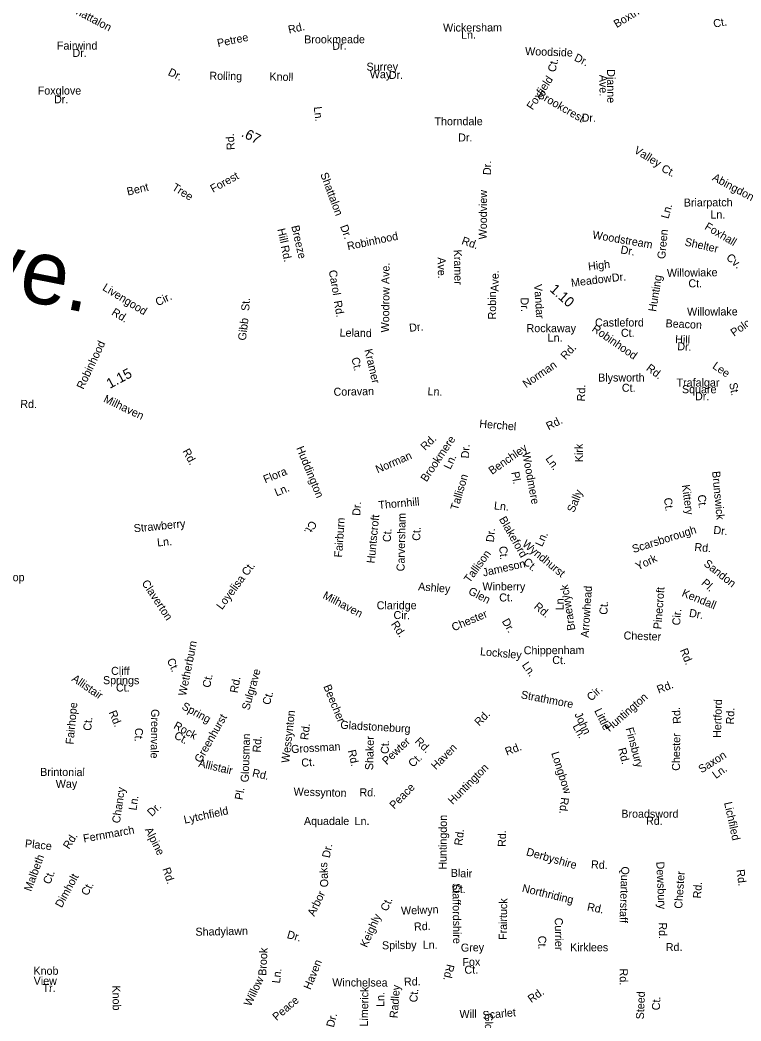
# Model space of a CAD drawing. Extents: x 1553981 to 1780076, y 812965 to 996873.
# Drawn here: x 1629823 to 1630892, y 848292 to 849777 of the extents above; entities that cross this region are included whole.
import ezdxf

# ---------------------------------------------------------------- set-up
doc = ezdxf.new("R2010")
doc.units = 0
for name, color, linetype in [('Exist Road Non-System Type 51 Label', 7, 'Continuous'), ('Exist Road Secondary Mileage Hundredths English Label', 7, 'Continuous'), ('Map Preparation Border Antique Large Shape', 7, 'Continuous')]:
    doc.layers.add(name, color=color, linetype=linetype)

msp = doc.modelspace()

# ---------------------------------------------------------------- texts
at = {"layer": 'Exist Road Non-System Type 51 Label'}
for s, height, rotation, p in [('Boxthorne', 11.87, 31.3922, (1630707.9, 849765)), ('Ct.', 11.88, 9.8757, (1630852.1, 849765.7)), ('Rd.', 11.88, 12.9036, (1630222.1, 849756.8)), ('Wickersham', 11.87, 0.1781, (1630450.4, 849759.9)), ('Ln.', 11.87, 0.1781, (1630477.2, 849749.3)), ('Petree', 11.88, 11.789, (1630116.7, 849736.8)), ('Brookmeade', 11.87, 0.1781, (1630244.5, 849742.4)), ('Dr.', 11.87, 0.8146, (1630286.2, 849732.8)), ('Woodside', 11.88, 358.1543, (1630571.9, 849725.1)), ('Ct.', 11.88, 77.4738, (1630616.9, 849699.1)), ('Dr.', 11.88, 333.7586, (1630643.8, 849717.4)), ('Surrey', 11.87, 0.1781, (1630336.9, 849701.9)), ('Way', 11.87, 0.1781, (1630341.8, 849690.7)), ('Dr.', 11.87, 0.1781, (1630370, 849689.7)), ('Dianne', 11.88, 270.4158, (1630693.5, 849704.1)), ('Rolling', 11.88, 359.1634, (1630103.8, 849688.6)), ('Knoll', 11.88, 358.1445, (1630192.8, 849687.6)), ('Foxfield', 11.88, 56.2308, (1630583.2, 849642.8)), ('Ave.', 11.88, 270.4158, (1630682.2, 849695.8)), ('Brookcrest', 11.88, 329.8936, (1630589.7, 849662.9)), ('Ln.', 11.87, 276.4955, (1630258.6, 849648.1)), ('Thorndale', 11.87, 0.1781, (1630437.7, 849620.9)), ('Dr.', 11.88, 359.1895, (1630655.8, 849626.4)), ('Rd.', 11.87, 93.6142, (1630141.6, 849584.6)), ('Dr.', 11.87, 0.1781, (1630472.8, 849596.9)), ('Valley', 11.88, 328.4345, (1630732.5, 849580.8)), ('Dr.', 11.88, 89.5136, (1630521.5, 849547.1)), ('Ct.', 11.88, 332.383, (1630773, 849553.2)), ('Forest', 11.88, 28.6979, (1630109.2, 849520.7)), ('Abingdon', 11.88, 331.74, (1630848.4, 849540)), ('Bent', 11.87, 13.7592, (1629983, 849516.6)), ('Tree', 11.88, 327.9451, (1630047.4, 849525.9)), ('Woodview', 11.88, 89.5136, (1630515.1, 849451.7)), ('Briarpatch', 11.88, 0.3783, (1630807.3, 849500.4)), ('Ln.', 11.88, 74.3344, (1630784.5, 849481.5)), ('Ln.', 11.88, 359.7932, (1630846.7, 849482.7)), ('Ave.', 95, 348.7973, (1629672.5, 849392)), ('Hill', 11.88, 282.9666, (1630204.5, 849466.7)), ('Breeze', 11.88, 282.763, (1630225.3, 849471.2)), ('Woodstream', 11.88, 350.2503, (1630671.2, 849453.2)), ('Green', 11.87, 84.6282, (1630779.7, 849422.2)), ('Foxhall', 11.88, 329.1319, (1630837.2, 849467.6)), ('Shelter', 11.88, 347.4622, (1630807.9, 849442.8)), ('Rd.', 11.88, 282.763, (1630209.6, 849441.5)), ('Kramer', 11.88, 271.2351, (1630466.2, 849436.4)), ('Dr.', 11.88, 350.2503, (1630712.9, 849431.1)), ('Ave.', 11.88, 271.2351, (1630442.2, 849425.1)), ('High', 11.88, 6.532, (1630666.1, 849405.6)), ('Cv.', 11.88, 318.2183, (1630869.3, 849423.3)), ('Carol', 11.88, 279.8235, (1630280.8, 849405.3)), ('Ave.', 11.87, 89.4313, (1630370.8, 849385.4)), ('Ave.', 11.88, 89.7261, (1630532.8, 849374.2)), ('Willowlake', 11.87, 0.7725, (1630782.4, 849396.1)), ('Meadow', 11.88, 7.1572, (1630640.9, 849381.3)), ('Dr.', 11.88, 5.4656, (1630701.1, 849388.8)), ('Hunting', 11.88, 80.7597, (1630766.2, 849343.9)), ('Ct.', 11.88, 359.3352, (1630814.1, 849380.7)), ('Livengood', 11.88, 328.3716, (1629944.4, 849377.2)), ('Woodrow', 11.88, 89.3796, (1630370.3, 849313.7)), ('Vandar', 11.88, 273.7771, (1630585.3, 849385)), ('Cir.', 11.88, 25.9069, (1630027.3, 849352.4)), ('St.', 11.88, 86.7419, (1630162.9, 849345.3)), ('Rd.', 11.88, 280.0506, (1630288.2, 849360)), ('Robin', 11.88, 89.7261, (1630528.9, 849333)), ('Dr.', 11.88, 272.5837, (1630565.2, 849365.3)), ('Rd.', 11.88, 328.3716, (1629957.8, 849340.6)), ('Willowlake', 11.88, 0.1325, (1630812.2, 849338.7)), ('Gibb', 11.87, 83.178, (1630157.9, 849301.2)), ('Beacon', 11.88, 357.401, (1630780.1, 849321.4)), ('Polo', 11.88, 34.8956, (1630881.8, 849307.1)), ('Leland', 11.88, 358.9235, (1630296.9, 849307.6)), ('Dr.', 11.88, 5.8843, (1630400.7, 849314.6)), ('Robinhood', 11.88, 64.5853, (1629917, 849228.4)), ('Hill', 11.88, 357.401, (1630794.3, 849297.9)), ('Kramer', 11.88, 283.2996, (1630333.6, 849287.8)), ('Rd.', 11.88, 47.0314, (1630632, 849272.4)), ('Dr.', 11.88, 357.401, (1630797.5, 849287.4)), ('Ct.', 11.88, 283.2996, (1630314.4, 849275.4)), ('Norman', 11.88, 34.4484, (1630573.5, 849230.9)), ('Lee', 11.88, 325.4495, (1630848.8, 849261.4)), ('Coravan', 11.88, 1.0678, (1630288.1, 849219.7)), ('Ln.', 11.88, 357.6763, (1630427.2, 849220.6)), ('Rd.', 11.88, 88.3833, (1630660.7, 849211.3)), ('St.', 11.87, 280.2859, (1630874.6, 849238.2)), ('Milhaven', 11.88, 334.6088, (1629945.8, 849211.1)), ('Herchel', 11.88, 355.2938, (1630503.8, 849172.7)), ('Rd.', 11.88, 26.9901, (1630606.8, 849168.5)), ('Rd.', 11.88, 44.536, (1630424, 849137.8)), ('Brookmere', 11.88, 55.9005, (1630425.8, 849091.1)), ('Rd.', 11.88, 298.9483, (1630063.5, 849137.5)), ('Huddington', 11.88, 292.2552, (1630232.4, 849142.2)), ('Dr.', 11.87, 87.3262, (1630488.8, 849126.7)), ('Benchley', 11.88, 34.9339, (1630523, 849102.3)), ('Kirk', 11.88, 90.2038, (1630657.7, 849121.3)), ('Norman', 11.88, 23.3308, (1630353.4, 849104.5)), ('Ln.', 11.88, 64.866, (1630461.3, 849109.6)), ('Woodmere', 11.88, 280.5077, (1630567.7, 849134.5)), ('Ln.', 11.88, 305.3065, (1630601.7, 849126.4)), ('Flora', 11.88, 22.2579, (1630186.7, 849089.7)), ('Brunswick', 11.87, 275.2973, (1630849.3, 849107.5)), ('Tallison', 11.88, 73.7258, (1630472.3, 849049.1)), ('Pl.', 11.88, 280.5077, (1630551.4, 849106.2)), ('Ln.', 11.88, 22.2579, (1630203.4, 849070.4)), ('Sally', 11.88, 67.7028, (1630644.6, 849045.7)), ('Kittery', 11.87, 278.1226, (1630804.3, 849087.1)), ('Thornhill', 11.88, 5.141, (1630355.1, 849051.7)), ('Ln.', 11.88, 354.3443, (1630525.5, 849051.3)), ('Ct.', 11.87, 278.1226, (1630777.7, 849067.8)), ('Ct.', 11.87, 275.2973, (1630828, 849072.6)), ('Dr.', 11.88, 86.0384, (1630327.5, 849041.4)), ('Strawberry', 11.88, 5.5425, (1629992.3, 849017.2)), ('Ct.', 11.87, 238.3786, (1630254.2, 849035.7)), ('Fairburn', 11.88, 86.0384, (1630300.6, 848979.6)), ('Huntscroft', 11.88, 84.5316, (1630348.9, 848970.8)), ('Carversham', 11.87, 88.8435, (1630393.2, 848959.3)), ('Blakeford', 11.88, 299.7713, (1630532.9, 849036.7)), ('Ct.', 11.88, 85.7668, (1630372.6, 849002.4)), ('Ct.', 11.87, 88.8435, (1630416.6, 849004.6)), ('Dr.', 11.87, 84.5537, (1630525.7, 849002.1)), ('Scarsborough', 11.875, 17.6674, (1630732.8, 848986.4)), ('Dr.', 11.88, 354.0217, (1630850.8, 849015.1)), ('Ln.', 11.88, 5.5425, (1630026.9, 848996.2)), ('Wyndhurst', 11.87, 320.5199, (1630566.8, 848998.1)), ('Ln.', 11.88, 65.2837, (1630597.2, 848994.9)), ('Tallison', 11.87, 53.81, (1630489.8, 848941.4)), ('Ct.', 11.88, 274.5531, (1630533.6, 848996.4)), ('Rd.', 11.88, 355.0182, (1630822.7, 848989.8)), ('Jameson', 11.88, 12.6818, (1630510.4, 848951.6)), ('Ct.', 11.88, 319.4659, (1630568.3, 848971.6)), ('York', 11.87, 25.4492, (1630739.4, 848960.6)), ('Sandon', 11.87, 321.5815, (1630835.9, 848968.8)), ('Ct.', 11.88, 53.1509, (1630160.1, 848951.6)), ('Claverton', 11.88, 303.5466, (1630002.9, 848942)), ('Loyelisa', 11.88, 53.1509, (1630122.6, 848901.6)), ('Pl.', 11.88, 317.8889, (1630832.4, 848940.8)), ('Milhaven', 11.88, 332.1808, (1630271, 848920.1)), ('Ashley', 11.88, 355.4223, (1630413.1, 848931.3)), ('Glen', 11.88, 332.6487, (1630486.8, 848926.3)), ('Winberry', 11.88, 359.6465, (1630508.7, 848931.3)), ('Braewyck', 11.88, 99.1579, (1630646.6, 848872.5)), ('Arrowhead', 11.88, 86.2124, (1630666.2, 848860.8)), ('Pinecroft', 11.88, 85.573, (1630773.9, 848873.1)), ('Kendall', 11.88, 337.7257, (1630803.4, 848922.9)), ('Claridge', 11.88, 0.1546, (1630352, 848903)), ('Ct.', 11.88, 0.6409, (1630533.7, 848914.6)), ('Ln.', 11.87, 89.1116, (1630629, 848901.5)), ('Cir.', 11.87, 359.0093, (1630376.8, 848888.7)), ('Chester', 11.88, 22.9264, (1630466.1, 848870.3)), ('Rd.', 11.88, 319.6172, (1630584.2, 848905.6)), ('Ct.', 11.88, 86.6633, (1630693.9, 848894.7)), ('Cir.', 11.88, 85.573, (1630801.8, 848878.9)), ('Dr.', 11.88, 350.0994, (1630814.5, 848892.2)), ('Rd.', 11.88, 303.714, (1630372.6, 848880.9)), ('Dr.', 11.88, 300.0169, (1630537.1, 848885.3)), ('Chester', 11.88, 358.1574, (1630717.9, 848858.4)), ('Wetherburn', 11.87, 78.546, (1630069.1, 848773.8)), ('Locksley', 11.87, 354.8455, (1630504.9, 848834.9)), ('Chippenham', 11.87, 0.2773, (1630570, 848836.3)), ('Rd.', 11.88, 292.0781, (1630801.3, 848842.4)), ('Ct.', 11.88, 293.8206, (1630040.6, 848827.5)), ('Ln.', 11.88, 304.7468, (1630566.7, 848820.2)), ('Ct.', 11.88, 359.1026, (1630612.2, 848822)), ('Cliff', 11.88, 359.8562, (1629958.1, 848805.8)), ('Sulgrave', 11.87, 74.0866, (1630162.9, 848752.6)), ('Allistair', 11.88, 325.5681, (1629898.7, 848797.7)), ('Springs', 11.88, 359.8562, (1629946.1, 848792)), ('Ct.', 11.87, 78.546, (1630104.9, 848786.1)), ('Rd.', 11.88, 79.5319, (1630145.7, 848778.2)), ('Rd.', 11.88, 21.0866, (1630770.1, 848777.9)), ('Ct.', 11.88, 359.8562, (1629965.3, 848781.1)), ('Beecher', 11.88, 292.1736, (1630272.6, 848788.7)), ('Strathmore', 11.88, 349.0968, (1630565.1, 848771.2)), ('Cir.', 11.88, 43.0647, (1630670.1, 848766.1)), ('Ct.', 11.87, 74.0866, (1630193.3, 848760.3)), ('Huntington', 11.88, 41.1128, (1630697.1, 848720.7)), ('Hertford', 11.87, 88.3163, (1630862.4, 848712.2)), ('Fairhope', 11.88, 84.5862, (1629902.3, 848702.2)), ('Rd.', 11.88, 292.0362, (1629954.5, 848750.3)), ('Greenvale', 11.88, 269.2383, (1630017.7, 848755.1)), ('Spring', 11.88, 331.2436, (1630061.7, 848755.8)), ('Wessynton', 11.87, 83.5865, (1630222.2, 848674.7)), ('Rd.', 11.88, 45.3748, (1630503.9, 848729.1)), ('Little', 11.88, 296.0144, (1630674.3, 848752.7)), ('Rd.', 11.88, 93.9483, (1630803.3, 848733.6)), ('Rd.', 11.87, 88.3163, (1630881.7, 848732.2)), ('Ct.', 11.88, 84.5862, (1629928.5, 848722.5)), ('Rock', 11.88, 331.2436, (1630049.7, 848727.1)), ('Greenhurst', 11.88, 60.219, (1630091.1, 848674.4)), ('Gladstoneburg', 11.875, 356.6584, (1630297.8, 848726)), ('John', 11.87, 295.1386, (1630645, 848747.4)), ('Ct.', 11.88, 268.0574, (1629993.7, 848727.3)), ('Ct.', 11.88, 331.2436, (1630050.5, 848712.5)), ('Rd.', 11.88, 82.6225, (1630250.2, 848708.7)), ('Ln.', 11.87, 298.8229, (1630642, 848729.7)), ('Finsbury', 11.88, 285.002, (1630720.9, 848726.3)), ('Glousman', 11.88, 88.2265, (1630162.1, 848646.3)), ('Rd.', 11.87, 85.8126, (1630179.6, 848690.3)), ('Shaker', 11.87, 88.3598, (1630346.6, 848664.4)), ('Ct.', 11.87, 88.3598, (1630369.8, 848688.4)), ('Pewter', 11.87, 43.7199, (1630366.8, 848671.6)), ('Rd.', 11.88, 315.8376, (1630407.7, 848706.2)), ('Chester', 11.87, 89.5554, (1630801.6, 848663.5)), ('Grossman', 11.87, 3.2688, (1630225.4, 848689.7)), ('Rd.', 11.87, 282.7231, (1630309.1, 848693.4)), ('Haven', 11.88, 45.3355, (1630439.7, 848664.2)), ('Rd.', 11.88, 21.0866, (1630545, 848685.9)), ('Longbow', 11.88, 287.6747, (1630610.6, 848689.8)), ('Rd.', 11.88, 285.002, (1630709.7, 848696)), ('Allistair', 11.88, 346.62, (1630087, 848669.7)), ('Ct.', 11.87, 3.2688, (1630240.5, 848669.6)), ('Ct.', 11.87, 43.7199, (1630405.6, 848667.8)), ('Saxon', 11.88, 32.6164, (1630833.7, 848659.6)), ('Brintonial', 11.88, 359.7474, (1629853, 848655.9)), ('Rd.', 11.88, 347.1539, (1630166.6, 848655.3)), ('Huntington', 11.88, 45.0883, (1630464.6, 848612.7)), ('Ln.', 11.88, 35.7842, (1630854.9, 848651.1)), ('Way', 11.87, 0.9148, (1629876.2, 848638.1)), ('Chancy', 11.87, 81.5292, (1629971.1, 848585.1)), ('Pl.', 11.88, 80.3066, (1630153, 848619.6)), ('Wessynton', 11.87, 358.3826, (1630228.6, 848626.9)), ('Rd.', 11.88, 359.4157, (1630326.4, 848625.7)), ('Peace', 11.88, 45.5988, (1630378, 848605.9)), ('Ln.', 11.87, 81.5292, (1629995.7, 848604.2)), ('Rd.', 11.88, 263.7807, (1630625.3, 848624.6)), ('Lichfiled', 11.87, 282.4681, (1630867, 848616.1)), ('Dr.', 11.88, 43.9881, (1630018.5, 848594.9)), ('Lytchfield', 11.88, 12.2052, (1630067.3, 848585)), ('Broadsword', 11.88, 359.9777, (1630714.7, 848593.9)), ('Aquadale', 11.88, 0.0294, (1630244.1, 848583.1)), ('Ln.', 11.88, 0.1121, (1630319.2, 848583)), ('Huntingdon', 11.88, 89.4901, (1630455.5, 848516.9)), ('Rd.', 11.87, 359.3455, (1630751.3, 848583.6)), ('Fernmarch', 11.88, 10.041, (1629917.8, 848557.1)), ('Alpine', 11.88, 296.5578, (1630007.8, 848576.3)), ('Rd.', 11.88, 83.0363, (1630478.6, 848552.1)), ('Rd.', 11.88, 89.0225, (1630543.4, 848550.5)), ('Place', 11.88, 353.7723, (1629830, 848550.1)), ('Rd.', 11.88, 57.3198, (1629895.9, 848546.3)), ('Dr.', 11.87, 78.98, (1630282.3, 848533.6)), ('Derbyshire', 11.88, 344.2276, (1630572.8, 848538.4)), ('Malbeth', 11.88, 69.675, (1629839.6, 848483.7)), ('Rd.', 11.88, 356.6379, (1630669.5, 848519.1)), ('Rd.', 11.88, 287.7932, (1630034.2, 848518.1)), ('Oaks', 11.87, 92.8866, (1630280.3, 848491.1)), ('Blair', 11.88, 357.9344, (1630461.6, 848506.3)), ('Quarterstaff', 11.875, 268.1774, (1630714.7, 848521.8)), ('Dewsbury', 11.88, 272.4251, (1630766.6, 848528.6)), ('Chester', 11.88, 86.1187, (1630804.9, 848458.6)), ('Rd.', 11.87, 277.288, (1630885.5, 848516.6)), ('Ct.', 11.88, 69.675, (1629867.8, 848494.3)), ('Dimholt', 11.88, 61.6823, (1629884.9, 848459.5)), ('Ct.', 11.88, 61.6823, (1629923.2, 848477.2)), ('Arbor', 11.87, 64.3648, (1630259.3, 848446.8)), ('Staffordshire', 11.875, 270.7025, (1630464.3, 848496.8)), ('Ct.', 11.88, 357.9344, (1630463.6, 848482.8)), ('Northriding', 11.875, 346.5423, (1630566.7, 848484.2)), ('Rd.', 11.88, 86.1187, (1630832.8, 848473.9)), ('Ct.', 11.88, 66.3224, (1630367.7, 848454.2)), ('Frairtuck', 11.88, 89.3364, (1630544.8, 848412.5)), ('Welwyn', 11.88, 2.3445, (1630388.3, 848450)), ('Rd.', 11.88, 348.8335, (1630663.2, 848456.5)), ('Keighly', 11.88, 65.7994, (1630337.4, 848400.5)), ('Rd.', 11.88, 2.3445, (1630407.5, 848426.5)), ('Currier', 11.88, 270.745, (1630616, 848445.6)), ('Shadylawn', 11.88, 1.1111, (1630083.4, 848418.8)), ('Dr.', 11.87, 344.0247, (1630218, 848415.7)), ('Rd.', 11.88, 270.3602, (1630770.3, 848438.7)), ('Spilsby', 11.88, 0.7689, (1630359.9, 848398.7)), ('Ln.', 11.87, 0.2406, (1630420.3, 848399.5)), ('Ct.', 11.88, 270.745, (1630591.4, 848418.8)), ('Brook', 11.88, 87.0503, (1630188.1, 848359.3)), ('Grey', 11.88, 1.2316, (1630476.9, 848395.2)), ('Kirklees', 11.88, 359.9346, (1630638.7, 848395.9)), ('Rd.', 11.88, 0.8989, (1630780.7, 848396)), ('Haven', 11.88, 67.8211, (1630253.8, 848338)), ('Fox', 11.88, 1.2316, (1630479.2, 848373.9)), ('Knob', 11.87, 359.8902, (1629843, 848361)), ('Ln.', 11.88, 83.5454, (1630208.5, 848347.8)), ('Rd.', 11.88, 257.0197, (1630456, 848377.5)), ('Ct.', 11.88, 1.2316, (1630482.2, 848362.4)), ('Rd.', 11.88, 270.4232, (1630712.3, 848370.2)), ('View', 11.87, 359.8902, (1629843.3, 848346.1)), ('Willow', 11.88, 64.6564, (1630165.1, 848313.2)), ('Winchelsea', 11.87, 359.8387, (1630286.1, 848343.7)), ('Rd.', 11.88, 1.1199, (1630392.5, 848344.8)), ('Tr.', 11.87, 359.8902, (1629856.5, 848335.5)), ('Knob', 11.87, 271.116, (1629960, 848345)), ('Limerick', 11.88, 88.9833, (1630338.8, 848284.2)), ('Radley', 11.88, 85.2954, (1630382.7, 848296.2)), ('Ct.', 11.88, 85.2954, (1630412.1, 848319.7)), ('Rd.', 11.88, 35.1897, (1630581.2, 848318.8)), ('Steed', 11.87, 87.6897, (1630748.1, 848294.7)), ('Peace', 11.88, 40.8114, (1630203.6, 848292.1)), ('Ln.', 11.88, 88.9833, (1630363.1, 848313.2)), ('Ct.', 11.87, 87.6897, (1630771.8, 848308.1)), ('Will', 11.87, 0.5668, (1630474.8, 848296.9)), ('Scarlet', 11.87, 5.294, (1630509.5, 848295)), ('Dr.', 11.87, 76.2693, (1630288.4, 848282.2)), ('Glocoustershire', 11.875, 270.6537, (1630512.2, 848303.9))]:
    msp.add_text(s, height=height, rotation=rotation, dxfattribs=at).set_placement(p)
for s, p in [('Fairwind', (1629877.8, 849733.2)), ('Dr.', (1629900.9, 849722.4)), ('Foxglove', (1629849.4, 849666.5)), ('Dr.', (1629873.5, 849653.6)), ('Castleford', (1630675.7, 849322.5)), ('Rockaway', (1630574.2, 849314.1)), ('Ct.', (1630714.1, 849307.2)), ('Ln.', (1630605.4, 849300)), ('Blysworth', (1630680.3, 849240.9)), ('Trafalgar', (1630796.6, 849233.5)), ('Ct.', (1630715.5, 849225.7)), ('Square', (1630804.6, 849223.5)), ('Dr.', (1630824, 849213.1)), ('Pinetop', (1629776, 848944.7))]:
    msp.add_text(s, height=11.88, dxfattribs=at).set_placement(p)
at = {"layer": 'Exist Road Secondary Mileage Hundredths English Label'}
for s, rotation, p in [('.67', 332.8207, (1630150.2, 849605.2)), ('1.10', 318.1417, (1630607.5, 849376)), ('1.15', 28.3152, (1629956.3, 849229.9))]:
    msp.add_text(s, height=15, rotation=rotation, dxfattribs=at).set_placement(p)
at = {"layer": 'Map Preparation Border Antique Large Shape'}
for s, height, rotation, p in [('Shattalon', 11.88, 332.0229, (1629895.7, 849791.3)), ('Dr.', 11.88, 333.8077, (1630041.5, 849695.9)), ('Shattalon', 11.88, 290.3652, (1630268.1, 849548.5)), ('Dr.', 11.87, 290.0192, (1630297.5, 849471)), ('Robinhood', 11.87, 11.9655, (1630309.4, 849435.6)), ('Rd.', 11.88, 341.0248, (1630476.9, 849445)), ('Robinhood', 11.88, 325.1315, (1630670, 849316.8)), ('Rd.', 11.88, 322.945, (1630750.6, 849258.6)), ('Rd.', 11.88, 358.9728, (1629823.4, 849201.9))]:
    msp.add_text(s, height=height, rotation=rotation, dxfattribs=at).set_placement(p)

doc.saveas('drawing.dxf')
